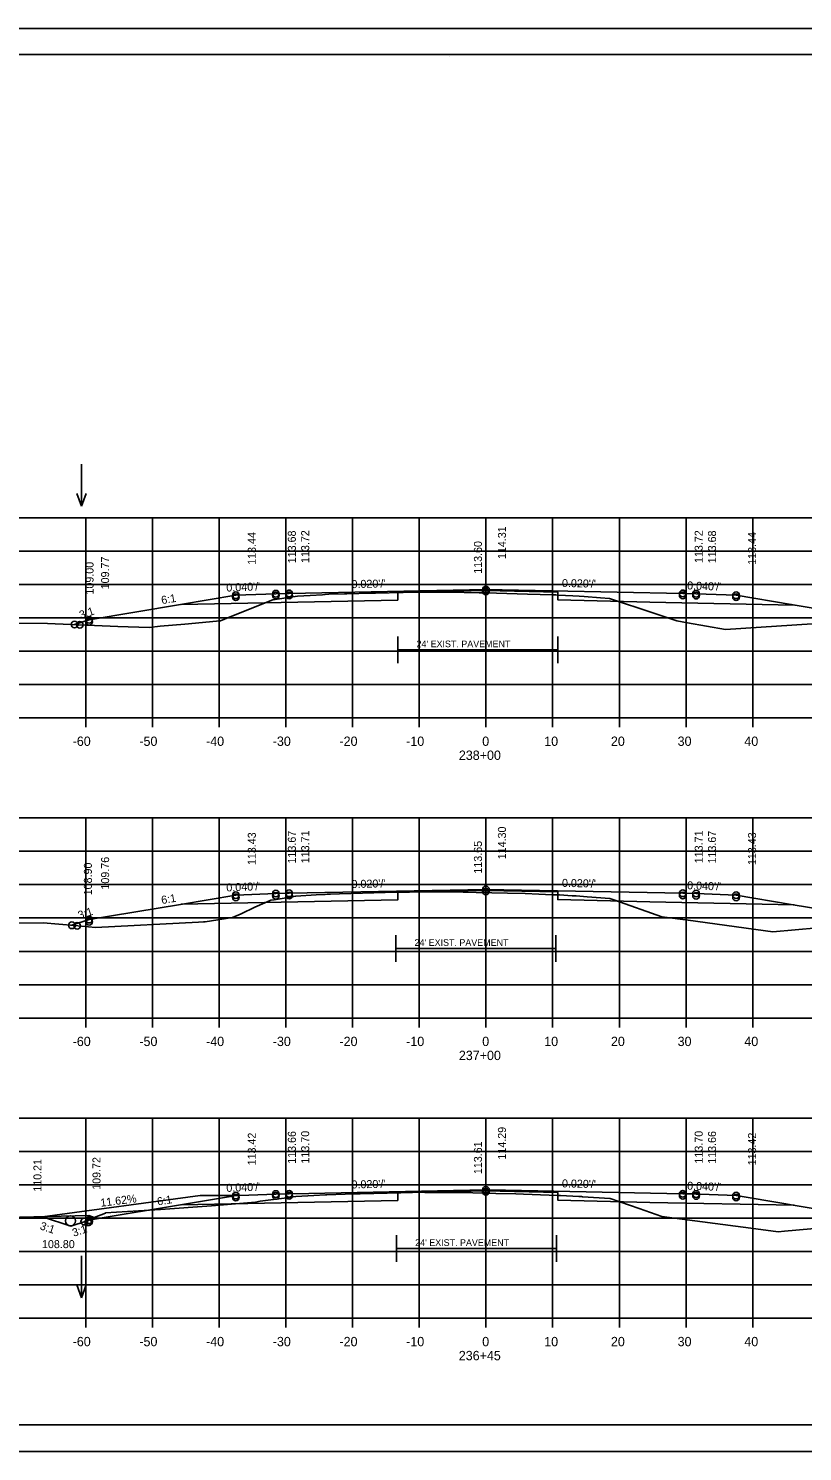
# Model space of a CAD drawing. Extents: x 1175611 to 1176402, y -433344 to -416213.
# Drawn here: x 1175712.4 to 1175828.4, y -422463.3 to -422250 of the extents above; entities that cross this region are included whole.
import ezdxf

# ---------------------------------------------------------------- set-up
doc = ezdxf.new("R2010")
doc.units = 0
for name, color, linetype in [('R_Alt Surface', 7, 'Continuous'), ('R_Axis', 7, 'Continuous'), ('R_Axis Annot', 7, 'Continuous'), ('R_Border', 7, 'Continuous'), ('R_Border Notes', 7, 'Continuous'), ('R_Drive', 7, 'Continuous'), ('R_Exist Surface', 7, 'Continuous'), ('R_Fin Surface', 7, 'Continuous'), ('R_Grid', 7, 'Continuous'), ('R_No Plot', 7, 'Continuous'), ('R_Water', 7, 'Continuous'), ('R_Water Annot', 7, 'Continuous'), ('R_Xsect Elev', 7, 'Continuous'), ('R_Xsect Slope', 7, 'Continuous')]:
    doc.layers.add(name, color=color, linetype=linetype)

msp = doc.modelspace()

# ---------------------------------------------------------------- linework, layer by layer
at = {"layer": 'R_Alt Surface'}
for p, q in [((1175767.74, -422343.1), (1175791.74, -422343.1)), ((1175767.46, -422387.88), (1175791.46, -422387.88)), ((1175767.55, -422432.86), (1175791.55, -422432.86))]:
    msp.add_line(p, q, dxfattribs=at)
for points in [[(1175735.29, -422336.3), (1175767.74, -422335.65), (1175767.74, -422334.49), (1175780.97, -422334.23), (1175791.74, -422334.44), (1175791.74, -422335.6), (1175805.54, -422335.95), (1175827.19, -422336.39)], [(1175767.74, -422345.1), (1175767.74, -422341.1)], [(1175791.74, -422345.1), (1175791.74, -422341.1)], [(1175735.29, -422381.25), (1175767.74, -422380.6), (1175767.74, -422379.45), (1175780.97, -422379.18), (1175791.74, -422379.4), (1175791.74, -422380.55), (1175805.54, -422380.91), (1175827.19, -422381.34)], [(1175767.46, -422389.88), (1175767.46, -422385.88)], [(1175791.46, -422389.88), (1175791.46, -422385.88)], [(1175735.29, -422426.29), (1175767.74, -422425.64), (1175767.74, -422424.49), (1175780.97, -422424.22), (1175791.74, -422424.44), (1175791.74, -422425.59), (1175805.54, -422425.95), (1175827.19, -422426.38)], [(1175767.55, -422434.86), (1175767.55, -422430.86)], [(1175791.55, -422434.86), (1175791.55, -422430.86)]]:
    msp.add_lwpolyline(points, dxfattribs=at)
at = {"layer": 'R_Axis'}
for p, q in [((1175640.97, -422353.31), (1175920.97, -422353.31)), ((1175720.97, -422354.71), (1175720.97, -422353.31)), ((1175730.97, -422354.71), (1175730.97, -422353.31)), ((1175740.97, -422354.71), (1175740.97, -422353.31)), ((1175750.97, -422354.71), (1175750.97, -422353.31)), ((1175760.97, -422354.71), (1175760.97, -422353.31)), ((1175770.97, -422354.71), (1175770.97, -422353.31)), ((1175780.97, -422354.71), (1175780.97, -422353.31)), ((1175790.97, -422354.71), (1175790.97, -422353.31)), ((1175800.97, -422354.71), (1175800.97, -422353.31)), ((1175810.97, -422354.71), (1175810.97, -422353.31)), ((1175820.97, -422354.71), (1175820.97, -422353.31)), ((1175640.97, -422398.31), (1175920.97, -422398.31)), ((1175720.97, -422399.71), (1175720.97, -422398.31)), ((1175730.97, -422399.71), (1175730.97, -422398.31)), ((1175740.97, -422399.71), (1175740.97, -422398.31)), ((1175750.97, -422399.71), (1175750.97, -422398.31)), ((1175760.97, -422399.71), (1175760.97, -422398.31)), ((1175770.97, -422399.71), (1175770.97, -422398.31)), ((1175780.97, -422399.71), (1175780.97, -422398.31)), ((1175790.97, -422399.71), (1175790.97, -422398.31)), ((1175800.97, -422399.71), (1175800.97, -422398.31)), ((1175810.97, -422399.71), (1175810.97, -422398.31)), ((1175820.97, -422399.71), (1175820.97, -422398.31)), ((1175640.97, -422443.31), (1175920.97, -422443.31)), ((1175720.97, -422444.71), (1175720.97, -422443.31)), ((1175730.97, -422444.71), (1175730.97, -422443.31)), ((1175740.97, -422444.71), (1175740.97, -422443.31)), ((1175750.97, -422444.71), (1175750.97, -422443.31)), ((1175760.97, -422444.71), (1175760.97, -422443.31)), ((1175770.97, -422444.71), (1175770.97, -422443.31)), ((1175780.97, -422444.71), (1175780.97, -422443.31)), ((1175790.97, -422444.71), (1175790.97, -422443.31)), ((1175800.97, -422444.71), (1175800.97, -422443.31)), ((1175810.97, -422444.71), (1175810.97, -422443.31)), ((1175820.97, -422444.71), (1175820.97, -422443.31))]:
    msp.add_line(p, q, dxfattribs=at)
at = {"layer": 'R_Border'}
for p, q in [((1175622.97, -422253.85), (1175939.15, -422253.85)), ((1175775.49, -422254.11), (1175775.49, -422254.11)), ((1175775.49, -422254.11), (1175775.49, -422254.11)), ((1175939.15, -422459.31), (1175622.97, -422459.31))]:
    msp.add_line(p, q, dxfattribs=at)
at = {"layer": 'R_Drive'}
msp.add_lwpolyline([(1175743.47, -422424.93), (1175738.13, -422424.93), (1175714.48, -422428.1)], dxfattribs=at)
at = {"layer": 'R_Exist Surface'}
for points in [[(1175701.28, -422339.13), (1175715.25, -422339.15), (1175725.78, -422339.61), (1175730.48, -422339.76), (1175732.14, -422339.57), (1175735.83, -422339.28), (1175740.59, -422338.8), (1175741.19, -422338.74), (1175742.37, -422338.26), (1175749, -422335.6), (1175751, -422335.3), (1175752.71, -422335.06), (1175754.64, -422334.95), (1175756.45, -422334.84), (1175756.81, -422334.82), (1175756.87, -422334.81), (1175757.4, -422334.78), (1175759.76, -422334.73), (1175760.11, -422334.72), (1175763.74, -422334.61), (1175764.42, -422334.59), (1175768.56, -422334.49), (1175769.68, -422334.46), (1175769.86, -422334.45), (1175774.94, -422334.44), (1175775.42, -422334.44), (1175779.95, -422334.55), (1175780.4, -422334.56), (1175781.02, -422334.58), (1175787.18, -422334.74), (1175790.99, -422334.87), (1175791.44, -422334.88), (1175791.81, -422334.9), (1175794.01, -422335.01), (1175794.93, -422335.06), (1175795.71, -422335.12), (1175798.15, -422335.3), (1175799.5, -422335.4), (1175806.16, -422337.62), (1175809.59, -422338.76), (1175811.2, -422339.06), (1175816.9, -422340.07), (1175829.88, -422339.19)], [(1175687.16, -422384.13), (1175714.58, -422384.03), (1175719.26, -422384.44), (1175722.43, -422384.72), (1175737.86, -422383.94), (1175738.62, -422383.91), (1175738.86, -422383.87), (1175742.95, -422383.25), (1175744.25, -422382.67), (1175746.32, -422381.71), (1175748.16, -422380.91), (1175748.71, -422380.66), (1175749.23, -422380.58), (1175752.46, -422380.03), (1175755.52, -422379.85), (1175756.88, -422379.77), (1175757.16, -422379.75), (1175757.65, -422379.73), (1175759.01, -422379.69), (1175762.45, -422379.58), (1175765.86, -422379.5), (1175768.71, -422379.44), (1175769.49, -422379.42), (1175770.76, -422379.39), (1175772.98, -422379.39), (1175775.62, -422379.4), (1175779.51, -422379.48), (1175784.21, -422379.59), (1175786.85, -422379.66), (1175788.91, -422379.74), (1175790.88, -422379.82), (1175791.72, -422379.85), (1175792, -422379.86), (1175793.88, -422379.97), (1175794.49, -422380), (1175795.07, -422380.03), (1175796.16, -422380.13), (1175799.57, -422380.4), (1175800.32, -422380.66), (1175807.36, -422383.13), (1175811.29, -422383.64), (1175824, -422385.37), (1175830.68, -422384.78)], [(1175709.02, -422428.23), (1175721.43, -422427.92), (1175722.25, -422428.22), (1175723.94, -422427.54), (1175723.94, -422427.54), (1175723.95, -422427.53), (1175732.2, -422427.01), (1175739.8, -422426.47), (1175746.43, -422425.93), (1175747.14, -422425.74), (1175751.5, -422425.2), (1175752.08, -422425.11), (1175752.49, -422425.07), (1175755.18, -422424.92), (1175756.93, -422424.83), (1175757.05, -422424.82), (1175757.12, -422424.81), (1175759.86, -422424.72), (1175760.87, -422424.68), (1175762.12, -422424.65), (1175768.2, -422424.49), (1175768.69, -422424.48), (1175769.11, -422424.47), (1175770.63, -422424.43), (1175771.83, -422424.44), (1175775.63, -422424.44), (1175777.26, -422424.48), (1175782.43, -422424.6), (1175785.47, -422424.67), (1175786.62, -422424.7), (1175790.43, -422424.84), (1175791.65, -422424.89), (1175792.14, -422424.91), (1175794.89, -422425.06), (1175795.14, -422425.07), (1175795.21, -422425.08), (1175795.3, -422425.08), (1175795.45, -422425.09), (1175799.61, -422425.38), (1175803.94, -422426.86), (1175807.35, -422428.07), (1175821.46, -422429.92), (1175824.77, -422430.37), (1175825.72, -422430.28), (1175838.15, -422429.14)]]:
    msp.add_lwpolyline(points, dxfattribs=at)
at = {"layer": 'R_Fin Surface'}
for points in [[(1175719.3, -422339.32), (1175721.47, -422338.6), (1175735.2, -422336.31), (1175743.47, -422334.93), (1175749.47, -422334.69), (1175751.47, -422334.65), (1175780.97, -422334.06), (1175810.47, -422334.65), (1175812.47, -422334.69), (1175818.47, -422334.93), (1175826.75, -422336.31), (1175840.47, -422338.6), (1175841.47, -422338.93), (1175841.62, -422338.88)], [(1175718.9, -422384.41), (1175721.47, -422383.55), (1175735.2, -422381.27), (1175743.47, -422379.89), (1175749.47, -422379.65), (1175751.47, -422379.61), (1175780.97, -422379.02), (1175810.47, -422379.61), (1175812.47, -422379.65), (1175818.47, -422379.89), (1175826.75, -422381.27), (1175840.47, -422383.55), (1175842.51, -422384.23)], [(1175714.48, -422428.1), (1175718.72, -422429.51), (1175721.04, -422428.74), (1175721.47, -422428.59), (1175722.85, -422428.37), (1175735.2, -422426.31), (1175742.65, -422425.07), (1175743.47, -422424.93), (1175744.07, -422424.9), (1175749.47, -422424.69), (1175751.27, -422424.65), (1175751.47, -422424.65), (1175754.42, -422424.59), (1175780.97, -422424.06), (1175783.92, -422424.12), (1175810.47, -422424.65), (1175812.27, -422424.68), (1175812.47, -422424.69), (1175813.07, -422424.71), (1175818.47, -422424.93), (1175825.92, -422426.17), (1175826.75, -422426.31), (1175839.1, -422428.37)]]:
    msp.add_lwpolyline(points, dxfattribs=at)
at = {"layer": 'R_Grid'}
for p, q in [((1175640.97, -422323.31), (1175920.97, -422323.31)), ((1175640.97, -422323.31), (1175920.97, -422323.31)), ((1175720.97, -422353.31), (1175720.97, -422323.31)), ((1175720.97, -422353.31), (1175720.97, -422323.31)), ((1175730.97, -422353.31), (1175730.97, -422323.31)), ((1175730.97, -422353.31), (1175730.97, -422323.31)), ((1175740.97, -422353.31), (1175740.97, -422323.31)), ((1175740.97, -422353.31), (1175740.97, -422323.31)), ((1175750.97, -422353.31), (1175750.97, -422323.31)), ((1175750.97, -422353.31), (1175750.97, -422323.31)), ((1175760.97, -422353.31), (1175760.97, -422323.31)), ((1175760.97, -422353.31), (1175760.97, -422323.31)), ((1175770.97, -422353.31), (1175770.97, -422323.31)), ((1175770.97, -422353.31), (1175770.97, -422323.31)), ((1175780.97, -422353.31), (1175780.97, -422323.31)), ((1175780.97, -422353.31), (1175780.97, -422323.31)), ((1175790.97, -422353.31), (1175790.97, -422323.31)), ((1175790.97, -422353.31), (1175790.97, -422323.31)), ((1175800.97, -422353.31), (1175800.97, -422323.31)), ((1175800.97, -422353.31), (1175800.97, -422323.31)), ((1175810.97, -422353.31), (1175810.97, -422323.31)), ((1175810.97, -422353.31), (1175810.97, -422323.31)), ((1175820.97, -422353.31), (1175820.97, -422323.31)), ((1175820.97, -422353.31), (1175820.97, -422323.31)), ((1175640.97, -422328.31), (1175920.97, -422328.31)), ((1175640.97, -422328.31), (1175920.97, -422328.31)), ((1175640.97, -422333.31), (1175920.97, -422333.31)), ((1175640.97, -422333.31), (1175920.97, -422333.31)), ((1175640.97, -422338.31), (1175920.97, -422338.31)), ((1175640.97, -422338.31), (1175920.97, -422338.31)), ((1175640.97, -422343.31), (1175920.97, -422343.31)), ((1175640.97, -422343.31), (1175920.97, -422343.31)), ((1175640.97, -422348.31), (1175920.97, -422348.31)), ((1175640.97, -422348.31), (1175920.97, -422348.31)), ((1175640.97, -422353.31), (1175920.97, -422353.31)), ((1175640.97, -422353.31), (1175920.97, -422353.31)), ((1175640.97, -422368.31), (1175920.97, -422368.31)), ((1175720.97, -422398.31), (1175720.97, -422368.31)), ((1175730.97, -422398.31), (1175730.97, -422368.31)), ((1175740.97, -422398.31), (1175740.97, -422368.31)), ((1175750.97, -422398.31), (1175750.97, -422368.31)), ((1175760.97, -422398.31), (1175760.97, -422368.31)), ((1175770.97, -422398.31), (1175770.97, -422368.31)), ((1175780.97, -422398.31), (1175780.97, -422368.31)), ((1175790.97, -422398.31), (1175790.97, -422368.31)), ((1175800.97, -422398.31), (1175800.97, -422368.31)), ((1175810.97, -422398.31), (1175810.97, -422368.31)), ((1175820.97, -422398.31), (1175820.97, -422368.31)), ((1175640.97, -422373.31), (1175920.97, -422373.31)), ((1175640.97, -422378.31), (1175920.97, -422378.31)), ((1175640.97, -422383.31), (1175920.97, -422383.31)), ((1175640.97, -422388.31), (1175920.97, -422388.31)), ((1175640.97, -422393.31), (1175920.97, -422393.31)), ((1175640.97, -422398.31), (1175920.97, -422398.31)), ((1175640.97, -422413.31), (1175920.97, -422413.31)), ((1175720.97, -422443.31), (1175720.97, -422413.31)), ((1175730.97, -422443.31), (1175730.97, -422413.31)), ((1175740.97, -422443.31), (1175740.97, -422413.31)), ((1175750.97, -422443.31), (1175750.97, -422413.31)), ((1175760.97, -422443.31), (1175760.97, -422413.31)), ((1175770.97, -422443.31), (1175770.97, -422413.31)), ((1175780.97, -422443.31), (1175780.97, -422413.31)), ((1175790.97, -422443.31), (1175790.97, -422413.31)), ((1175800.97, -422443.31), (1175800.97, -422413.31)), ((1175810.97, -422443.31), (1175810.97, -422413.31)), ((1175820.97, -422443.31), (1175820.97, -422413.31)), ((1175640.97, -422418.31), (1175920.97, -422418.31)), ((1175640.97, -422423.31), (1175920.97, -422423.31)), ((1175640.97, -422428.31), (1175920.97, -422428.31)), ((1175640.97, -422433.31), (1175920.97, -422433.31)), ((1175640.97, -422438.31), (1175920.97, -422438.31)), ((1175640.97, -422443.31), (1175920.97, -422443.31))]:
    msp.add_line(p, q, dxfattribs=at)
at = {"layer": 'R_No Plot'}
for p, q in [((1175610.57, -422249.96), (1175943.91, -422249.96)), ((1175610.57, -422463.29), (1175943.91, -422463.29))]:
    msp.add_line(p, q, dxfattribs=at)
msp.add_lwpolyline([(1175610.57, -422249.96), (1175943.91, -422249.96), (1175943.91, -422463.3), (1175610.57, -422463.3)], close=True, dxfattribs=at)
for centre in [(1175780.97, -422334.06), (1175743.47, -422334.93), (1175743.47, -422335.22), (1175749.47, -422334.69), (1175749.47, -422334.98), (1175751.47, -422334.65), (1175751.47, -422334.94), (1175780.97, -422334.35), (1175810.47, -422334.65), (1175810.47, -422334.94), (1175812.47, -422334.69), (1175812.47, -422334.98), (1175818.47, -422334.93), (1175818.47, -422335.22), (1175719.3, -422339.32), (1175719.3, -422339.32), (1175720.07, -422339.36), (1175721.47, -422338.6), (1175721.47, -422338.89), (1175780.97, -422379.02), (1175743.47, -422379.89), (1175743.47, -422380.22), (1175749.47, -422379.65), (1175749.47, -422379.98), (1175751.47, -422379.61), (1175751.47, -422379.94), (1175780.97, -422379.35), (1175810.47, -422379.61), (1175810.47, -422379.94), (1175812.47, -422379.65), (1175812.47, -422379.98), (1175818.47, -422379.89), (1175818.47, -422380.22), (1175718.9, -422384.41), (1175718.9, -422384.41), (1175719.68, -422384.48), (1175721.47, -422383.55), (1175721.47, -422383.88), (1175743.47, -422424.93), (1175743.47, -422425.22), (1175749.47, -422424.69), (1175749.47, -422424.98), (1175751.47, -422424.65), (1175751.47, -422424.94), (1175780.97, -422424.06), (1175780.97, -422424.35), (1175810.47, -422424.65), (1175810.47, -422424.94), (1175812.47, -422424.69), (1175812.47, -422424.98), (1175818.47, -422424.93), (1175818.47, -422425.22), (1175720.75, -422428.83), (1175721.34, -422428.93), (1175721.47, -422428.59), (1175721.47, -422428.88)]:
    msp.add_circle(centre, 0.5, dxfattribs=at)
at = {"layer": 'R_Water'}
msp.add_circle((1175718.67, -422428.7), 0.75, dxfattribs=at)
at = {"layer": 'R_Water Annot'}
for p, q in [((1175720.35, -422315.29), (1175720.35, -422321.57)), ((1175720.35, -422321.57), (1175719.65, -422319.65)), ((1175720.35, -422321.57), (1175721.05, -422319.65)), ((1175720.35, -422433.94), (1175720.35, -422440.23)), ((1175720.35, -422440.23), (1175719.65, -422438.3)), ((1175720.35, -422440.23), (1175721.05, -422438.3))]:
    msp.add_line(p, q, dxfattribs=at)

# ---------------------------------------------------------------- texts
at = {"layer": 'R_Alt Surface'}
for p in [(1175770.56, -422342.72), (1175770.27, -422387.49), (1175770.36, -422432.47)]:
    msp.add_text("24' EXIST. PAVEMENT", height=1, dxfattribs=at).set_placement(p)
at = {"layer": 'R_Axis Annot'}
for s, p in [('-60', (1175719.01, -422357.51)), ('-50', (1175729.01, -422357.51)), ('-40', (1175739.01, -422357.51)), ('-30', (1175749.01, -422357.51)), ('-20', (1175759.01, -422357.51)), ('-10', (1175769.01, -422357.51)), ('0', (1175780.41, -422357.51)), ('10', (1175789.71, -422357.51)), ('20', (1175799.71, -422357.51)), ('30', (1175809.71, -422357.51)), ('40', (1175819.71, -422357.51)), ('238+00', (1175776.91, -422359.61)), ('-60', (1175719.01, -422402.51)), ('-50', (1175729.01, -422402.51)), ('-40', (1175739.01, -422402.51)), ('-30', (1175749.01, -422402.51)), ('-20', (1175759.01, -422402.51)), ('-10', (1175769.01, -422402.51)), ('0', (1175780.41, -422402.51)), ('10', (1175789.71, -422402.51)), ('20', (1175799.71, -422402.51)), ('30', (1175809.71, -422402.51)), ('40', (1175819.71, -422402.51)), ('237+00', (1175776.91, -422404.61)), ('-60', (1175719.01, -422447.51)), ('-50', (1175729.01, -422447.51)), ('-40', (1175739.01, -422447.51)), ('-30', (1175749.01, -422447.51)), ('-20', (1175759.01, -422447.51)), ('-10', (1175769.01, -422447.51)), ('0', (1175780.41, -422447.51)), ('10', (1175789.71, -422447.51)), ('20', (1175799.71, -422447.51)), ('30', (1175809.71, -422447.51)), ('40', (1175819.71, -422447.51)), ('236+45', (1175776.9, -422449.61))]:
    msp.add_text(s, height=1.4, dxfattribs=at).set_placement(p)
at = {"layer": 'R_Border Notes'}
msp.add_text('108.80', height=1.2, dxfattribs=at).set_placement((1175714.41, -422432.8))
at = {"layer": 'R_Drive'}
msp.add_text('11.62%', height=1.2, rotation=7.1649, dxfattribs=at).set_placement((1175723.24, -422426.61))
at = {"layer": 'R_Xsect Elev'}
for s, p in [('114.31', (1175783.97, -422329.5)), ('113.44', (1175746.47, -422330.37)), ('113.68', (1175752.47, -422330.13)), ('113.72', (1175754.47, -422330.09)), ('113.60', (1175780.37, -422331.71)), ('113.72', (1175813.47, -422330.09)), ('113.68', (1175815.47, -422330.13)), ('113.44', (1175821.47, -422330.37)), ('109.77', (1175724.47, -422334.04)), ('109.00', (1175722.14, -422334.82)), ('114.30', (1175783.97, -422374.51)), ('113.43', (1175746.47, -422375.38)), ('113.67', (1175752.47, -422375.14)), ('113.71', (1175754.47, -422375.1)), ('113.65', (1175780.37, -422376.66)), ('113.71', (1175813.47, -422375.1)), ('113.67', (1175815.47, -422375.14)), ('113.43', (1175821.47, -422375.38)), ('109.76', (1175724.47, -422379.05)), ('108.90', (1175721.89, -422379.91)), ('114.29', (1175783.97, -422419.53)), ('113.42', (1175746.47, -422420.4)), ('113.66', (1175752.47, -422420.16)), ('113.70', (1175754.47, -422420.12)), ('113.61', (1175780.37, -422421.71)), ('113.70', (1175813.47, -422420.12)), ('113.66', (1175815.47, -422420.16)), ('113.42', (1175821.47, -422420.4)), ('110.21', (1175714.33, -422424.35)), ('109.72', (1175723.18, -422424.06))]:
    msp.add_text(s, height=1.2, rotation=90, dxfattribs=at).set_placement(p)
at = {"layer": 'R_Xsect Slope'}
for s, rotation, p in [("0.040'/'", 2.2906, (1175742.07, -422334.39)), ("0.020'/'", 1.1458, (1175760.83, -422333.86)), ("0.020'/'", 358.8542, (1175792.36, -422333.69)), ("0.040'/'", 357.7094, (1175811.12, -422334.04)), ('6:1', 9.4623, (1175732.39, -422336.27)), ('3:1', 18.4349, (1175720.23, -422338.49)), ("0.040'/'", 2.2906, (1175742.07, -422379.34)), ("0.020'/'", 1.1458, (1175760.83, -422378.82)), ("0.020'/'", 358.8542, (1175792.36, -422378.64)), ("0.040'/'", 357.7094, (1175811.12, -422378.99)), ('6:1', 9.4623, (1175732.39, -422381.23)), ('3:1', 18.4349, (1175720.03, -422383.51)), ("0.040'/'", 2.2906, (1175742.07, -422424.38)), ("0.020'/'", 1.1458, (1175760.83, -422423.86)), ("0.020'/'", 358.8542, (1175792.36, -422423.69)), ("0.040'/'", 357.7094, (1175811.12, -422424.03)), ('6:1', 9.4623, (1175731.77, -422426.42)), ('3:1', 341.5651, (1175714, -422429.95)), ('3:1', 18.4349, (1175719.17, -422431.11))]:
    msp.add_text(s, height=1.2, rotation=rotation, dxfattribs=at).set_placement(p)

doc.saveas('drawing.dxf')
